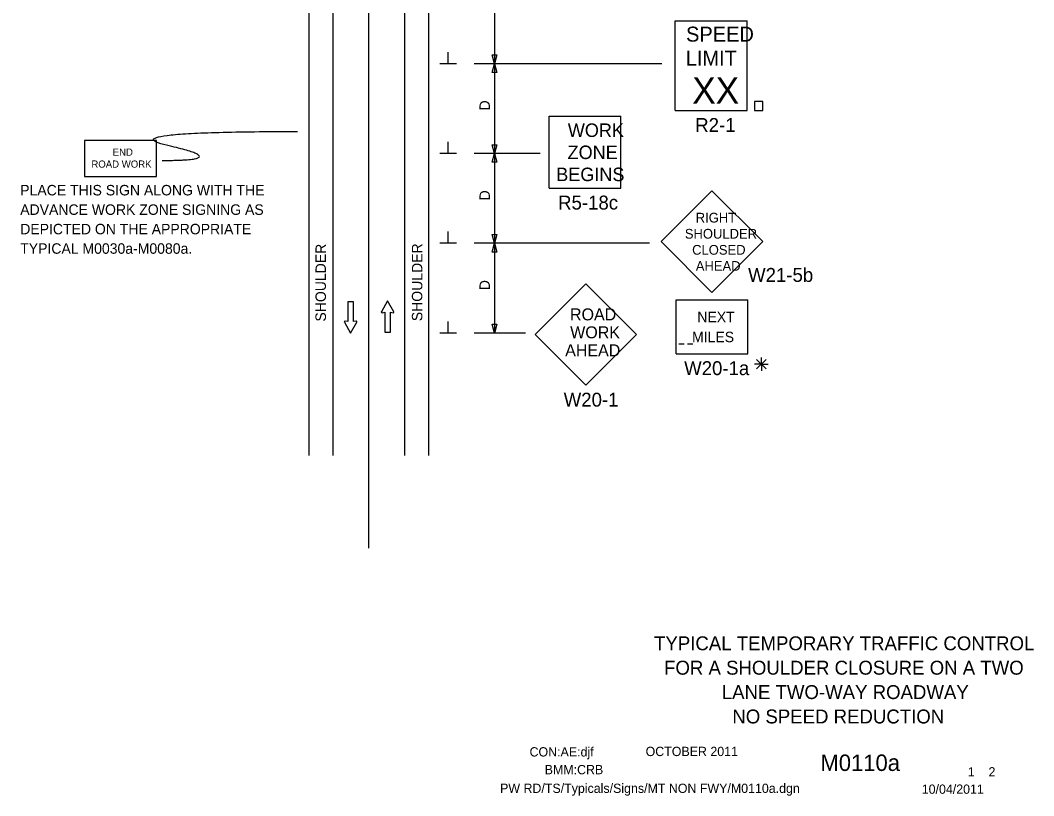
# Model space of a CAD drawing. Extents: x 16750 to 18471, y 7218 to 8211.
# Drawn here: x 16750 to 17428, y 7218 to 7736 of the extents above; entities that cross this region are included whole.
import ezdxf

# ---------------------------------------------------------------- set-up
doc = ezdxf.new("R2010")
doc.units = 0
for name, color, linetype in [('BORDER', 7, 'Continuous'), ('BORDER_SIGNAL_WO', 7, 'Continuous'), ('Level 6', 7, 'Continuous'), ('MT_SCRATCH_LEVEL_E', 7, 'Continuous'), ('PAVT_EDGE_EX', 7, 'Continuous'), ('TRAFFIC_SIGNS_PR', 7, 'Continuous'), ('TYPICAL_TEXT_DIMEN_PR', 7, 'Continuous')]:
    doc.layers.add(name, color=color, linetype=linetype)

msp = doc.modelspace()

# ---------------------------------------------------------------- linework, layer by layer
at = {"layer": 'Level 6'}
msp.add_lwpolyline([(17241.15, 7675.96), (17246.74, 7675.96), (17246.74, 7682.13), (17241.15, 7682.13)], close=True, dxfattribs=at)
at = {"layer": 'MT_SCRATCH_LEVEL_E'}
for p, q in [((16972.86, 7548.17), (16969.12, 7548.17)), ((16969.12, 7548.17), (16969.12, 7534.91)), ((16972.86, 7548.17), (16969.12, 7548.17)), ((16969.12, 7548.17), (16969.12, 7534.91)), ((16972.86, 7534.91), (16972.86, 7548.17)), ((16972.86, 7534.91), (16972.86, 7548.17)), ((16995.75, 7548.82), (16991.64, 7541.58)), ((16995.75, 7548.82), (16991.64, 7541.58)), ((16999.89, 7541.58), (16995.75, 7548.82)), ((16999.89, 7541.58), (16995.75, 7548.82)), ((16992.12, 7540.9), (16993.9, 7541.21)), ((16992.12, 7540.9), (16993.9, 7541.21)), ((16993.9, 7541.21), (16993.9, 7527.96)), ((16993.9, 7541.21), (16993.9, 7527.96)), ((16997.64, 7527.96), (16997.64, 7541.21)), ((16997.64, 7541.21), (16999.42, 7540.9)), ((16997.64, 7527.96), (16997.64, 7541.21)), ((16997.64, 7541.21), (16999.42, 7540.9)), ((16966.86, 7534.54), (16971.01, 7527.3)), ((16966.86, 7534.54), (16971.01, 7527.3)), ((16969.12, 7534.91), (16967.34, 7535.22)), ((16969.12, 7534.91), (16967.34, 7535.22)), ((16971.01, 7527.3), (16975.12, 7534.54)), ((16971.01, 7527.3), (16975.12, 7534.54)), ((16974.64, 7535.22), (16972.86, 7534.91)), ((16974.64, 7535.22), (16972.86, 7534.91)), ((16993.9, 7527.96), (16997.64, 7527.96)), ((16993.9, 7527.96), (16997.64, 7527.96))]:
    msp.add_line(p, q, dxfattribs=at)
for centre, start, end in [((16992.04, 7541.36), 150.42484, 279.96381), ((16992.04, 7541.36), 150.42484, 279.96381), ((16999.48, 7541.36), 260.03619, 29.77312), ((16999.48, 7541.36), 260.03619, 29.77312), ((16967.27, 7534.76), 80.03619, 209.77312), ((16967.27, 7534.76), 80.03619, 209.77312), ((16974.71, 7534.76), 330.42484, 99.96381), ((16974.71, 7534.76), 330.42484, 99.96381)]:
    msp.add_arc(centre, 0.463, start, end, dxfattribs=at)
at = {"layer": 'PAVT_EDGE_EX'}
for p, q in [((16943.15, 8180.56), (16943.15, 7445.4)), ((16959.15, 8180.56), (16959.15, 7445.4)), ((16983.15, 7383.56), (16983.15, 8180.56)), ((17007.15, 8180.56), (17007.15, 7445.4)), ((17023.15, 8180.56), (17023.15, 7445.4))]:
    msp.add_line(p, q, dxfattribs=at)
for points in [[(16983.15, 7645.4), (16983.15, 7670.4)], [(16983.15, 7545.4), (16983.15, 7570.4)], [(16983.15, 7445.4), (16983.15, 7470.4)]]:
    msp.add_lwpolyline(points, dxfattribs=at)
at = {"layer": 'TRAFFIC_SIGNS_PR'}
for p, q in [((17188.13, 7735.96), (17236.13, 7735.96)), ((17188.13, 7675.96), (17188.13, 7735.96)), ((17236.13, 7675.96), (17236.13, 7735.96)), ((17103.77, 7624.13), (17103.77, 7672.13)), ((17103.77, 7672.13), (17151.77, 7672.13)), ((17151.77, 7624.13), (17151.77, 7672.13)), ((17188.13, 7675.96), (17236.13, 7675.96)), ((17103.77, 7624.13), (17151.77, 7624.13)), ((17212.62, 7622.36), (17178.68, 7588.42)), ((17246.57, 7588.42), (17212.62, 7622.36)), ((17178.68, 7588.42), (17212.62, 7554.48)), ((17212.62, 7554.48), (17246.57, 7588.42)), ((17128.31, 7560.29), (17094.37, 7526.35)), ((17162.25, 7526.35), (17128.31, 7560.29)), ((17188.62, 7513.48), (17188.62, 7549.48)), ((17188.62, 7549.48), (17236.62, 7549.48)), ((17236.62, 7513.48), (17236.62, 7549.48)), ((17094.37, 7526.35), (17128.31, 7492.41)), ((17128.31, 7492.41), (17162.25, 7526.35)), ((17190.48, 7520.08), (17193.98, 7520.08)), ((17196.28, 7520.08), (17199.78, 7520.08)), ((17188.62, 7513.48), (17236.62, 7513.48))]:
    msp.add_line(p, q, dxfattribs=at)
msp.add_lwpolyline([(16793.2, 7631.89), (16841.2, 7631.89), (16841.2, 7655.89), (16793.2, 7655.89)], close=True, dxfattribs=at)
msp.add_open_spline([(16845.07, 7642.65), (16892.31, 7642.65), (16807.28, 7661.99), (16935.57, 7661.99)], degree=2, dxfattribs=at)
at = {"layer": 'TYPICAL_TEXT_DIMEN_PR'}
for p, q in [((17067.15, 7767.3), (17067.15, 7707.85)), ((17036.27, 7707.3), (17036.27, 7715.08)), ((17067.15, 7707.3), (17065.58, 7713.16)), ((17065.58, 7713.16), (17067.15, 7713.16)), ((17067.15, 7713.16), (17068.73, 7713.16)), ((17068.73, 7713.16), (17067.15, 7707.3)), ((17041.89, 7707.3), (17030.64, 7707.3)), ((17179.06, 7707.3), (17053.58, 7707.3)), ((17065.58, 7701.44), (17067.15, 7707.3)), ((17067.15, 7707.3), (17068.73, 7701.44)), ((17067.15, 7707.3), (17067.15, 7647.3)), ((17067.15, 7701.44), (17065.58, 7701.44)), ((17068.73, 7701.44), (17067.15, 7701.44)), ((17036.27, 7647.3), (17036.27, 7655.08)), ((17067.15, 7647.3), (17065.58, 7653.16)), ((17065.58, 7653.16), (17067.15, 7653.16)), ((17067.15, 7653.16), (17068.73, 7653.16)), ((17068.73, 7653.16), (17067.15, 7647.3)), ((17041.89, 7647.3), (17030.64, 7647.3)), ((17097.79, 7647.3), (17053.58, 7647.3)), ((17065.58, 7641.44), (17067.15, 7647.3)), ((17067.15, 7647.3), (17068.73, 7641.44)), ((17067.15, 7647.3), (17067.15, 7587.36)), ((17067.15, 7641.44), (17065.58, 7641.44)), ((17068.73, 7641.44), (17067.15, 7641.44)), ((17036.27, 7587.3), (17036.27, 7595.08)), ((17067.15, 7587.3), (17065.58, 7593.16)), ((17065.58, 7593.16), (17067.15, 7593.16)), ((17067.15, 7593.16), (17068.73, 7593.16)), ((17068.73, 7593.16), (17067.15, 7587.3)), ((17041.89, 7587.3), (17030.64, 7587.3)), ((17170.89, 7587.3), (17053.58, 7587.3)), ((17065.58, 7581.44), (17067.15, 7587.3)), ((17067.15, 7587.3), (17068.73, 7581.44)), ((17067.15, 7587.3), (17067.15, 7527.3)), ((17067.15, 7581.44), (17065.58, 7581.44)), ((17068.73, 7581.44), (17067.15, 7581.44)), ((17036.27, 7527.3), (17036.27, 7535.08)), ((17067.15, 7527.3), (17065.58, 7533.16)), ((17065.58, 7533.16), (17067.15, 7533.16)), ((17067.15, 7533.16), (17068.73, 7533.16)), ((17068.73, 7533.16), (17067.15, 7527.3)), ((17041.89, 7527.3), (17030.64, 7527.3)), ((17087.93, 7527.3), (17053.58, 7527.3)), ((17242.49, 7509.66), (17248.86, 7503.29)), ((17248.86, 7509.66), (17242.49, 7503.29)), ((17245.68, 7506.48), (17245.68, 7510.93)), ((17245.68, 7506.48), (17241.14, 7506.48)), ((17245.68, 7506.48), (17248.86, 7506.48)), ((17245.68, 7506.48), (17250.15, 7506.48)), ((17245.68, 7506.48), (17245.68, 7501.98))]:
    msp.add_line(p, q, dxfattribs=at)

# ---------------------------------------------------------------- texts
at = {"layer": 'BORDER'}
for s, p in [('TYPICAL TEMPORARY TRAFFIC CONTROL', (17173.94, 7315.29)), ('FOR A SHOULDER CLOSURE ON A TWO', (17180.63, 7298.99)), ('LANE TWO-WAY ROADWAY', (17219.22, 7282.69)), ('NO SPEED REDUCTION', (17226.28, 7266.39))]:
    msp.add_text(s, height=9.3, dxfattribs=at).set_placement(p)
at = {"layer": 'BORDER_SIGNAL_WO'}
for s, height, p in [('CON:AE:djf', 6.2, (17090.69, 7244.31)), ('    OCTOBER 2011    ', 6.2, (17159.08, 7244.59)), ('    M0110a    ', 11, (17268.86, 7234.63)), ('BMM:CRB   ', 6.2, (17100.81, 7232.42)), (' 1    2 ', 6.2, (17381.45, 7230.95)), ('PW RD/TS/Typicals/Signs/MT NON FWY/M0110a.dgn', 6.2, (17070.98, 7219.96)), ('10/04/2011    ', 6.2, (17352.93, 7219.38))]:
    msp.add_text(s, height=height, dxfattribs=at).set_placement(p)
at = {"layer": 'TRAFFIC_SIGNS_PR'}
for s, height, p in [('SPEED', 10, (17195.34, 7722.04)), ('LIMIT', 10, (17195.14, 7706.04)), ('XX', 17.538, (17199.52, 7680.66)), ('R2-1', 9.3, (17201.47, 7661.66)), ('WORK', 9.021, (17116.27, 7658.34)), ('ZONE', 9.021, (17116.12, 7643.57)), ('END', 4.789, (16811.95, 7645.8)), ('ROAD WORK', 4.789, (16797.71, 7637.82)), ('BEGINS', 9.021, (17108.53, 7628.81)), ('PLACE THIS SIGN ALONG WITH THE', 7, (16750.14, 7619.28)), ('R5-18c', 9.3, (17109.78, 7609.83)), ('ADVANCE WORK ZONE SIGNING AS', 7, (16750.14, 7606.28)), ('RIGHT', 6.5, (17201.78, 7601.15)), ('DEPICTED ON THE APPROPRIATE', 7, (16750.14, 7593.28)), ('SHOULDER', 6.5, (17194.51, 7590.4)), ('TYPICAL M0030a-M0080a.', 7, (16750.14, 7580.28)), ('CLOSED', 6.5, (17199.39, 7579.65)), ('AHEAD', 6.5, (17201.84, 7568.9)), ('W21-5b', 9.3, (17236.8, 7561.49)), ('ROAD', 8, (17117.74, 7535.77)), ('NEXT', 7, (17202.88, 7534.48)), ('WORK', 8, (17117.87, 7523.77)), ('   MILES', 7, (17191.54, 7521.18)), ('AHEAD', 8, (17114.51, 7511.77)), ('W20-1a', 9.3, (17194.05, 7499.18)), ('W20-1', 9.3, (17113.52, 7478.11))]:
    msp.add_text(s, height=height, dxfattribs=at).set_placement(p)
at = {"layer": 'TYPICAL_TEXT_DIMEN_PR'}
for s, p in [('D', (17064.19, 7676.03)), ('D', (17064.19, 7615.92)), ('SHOULDER', (16954.55, 7534.96)), ('SHOULDER', (17019, 7535.21)), ('D', (17064.19, 7555.92))]:
    msp.add_text(s, height=7, rotation=90, dxfattribs=at).set_placement(p)

doc.saveas('drawing.dxf')
